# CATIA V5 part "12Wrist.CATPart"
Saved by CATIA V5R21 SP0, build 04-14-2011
Part number: Wrist
Bounding box of the stored display mesh (mm): x -30 to 20.5, y -307.172 to -247.172, z 287.191 to 317.191
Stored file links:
  F:\教程\Robotic_Arm_Arduino_Kinect\机械臂CAD\Arm_Detailed_Design\Wrist.CATPart
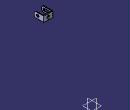
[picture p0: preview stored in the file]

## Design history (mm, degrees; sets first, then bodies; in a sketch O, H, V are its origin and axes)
Body1 (main body)
  DatumSurface1
  DatumCurve1
  DatumCurve2
  Plane1: stored without definition
  Plane2: stored without definition
  DatumCurve3
  Sketch1 on face of DatumSurface1, origin (0, -247.172, 0), H (-1, 0, 0), V (0, 0, 1)
    circle A1 centre (3, 310.6906) radius 1.25
    reference projected circle E1 centre (3, 310.6906) radius 1.25 from edge of DatumCurve2
    circle A2 centre (-5.5, 302.1906) radius 1.25
    circle A3 centre (3, 293.6906) radius 1.25
    circle A4 centre (11.5, 302.1906) radius 1.25
    line L1 (27, 317.1906) -> (-17.5, 317.1906)
    line L2 (-17.5, 317.1906) -> (-17.5, 287.1906)
    line L3 (-17.5, 287.1906) -> (27, 287.1906)
    line L4 (27, 287.1906) -> (27, 317.1906)
    reference intersected line E2 through (0, 302.1906) direction (-1, 0) from Plane1
    reference intersected line E3 through (3, 0) direction (0, -1) from Plane2
    circle A5 centre (3, 302.1906) radius 6
    reference projected circle E4 centre (3, 302.1906) radius 6 from edge of DatumCurve3
    length L2 = 30
    distance L1 E2 = 15
    length L3 = 44.5
    distance L2 E3 = 20.5
    coincidence: A1 E1, A5 E4
    horizontal: L1 H, L3 H
    vertical: L2 V, L4 V
  Pad1: profile Sketch1, direction (0, -1, 0), length 5
  Plane3 to Plane6: stored without definition
  Sketch2 on face of Pad1 from Sketch1.L4, origin (-27, 0, 0), H (0, -1, 0), V (0, 0, 1)
    point P1 (247.172, 317.1906)
    line L1 (247.172, 317.1906) -> (295.172, 317.1906)
    line L2 (307.172, 305.1906) -> (307.172, 299.1906)
    line L3 (295.172, 287.1906) -> (247.172, 287.1906)
    line L4 (247.172, 287.1906) -> (247.172, 317.1906)
    point P2 (307.172, 317.1906)
    reference projected line E1 (247.172, 317.1906) -> (252.172, 317.1906) from edge [face of Pad1 from Sketch1.L4 | face of Pad1 from Sketch1.L1]
    reference projected line E2 (247.172, 287.1906) -> (252.172, 287.1906) from edge [face of Pad1 from Sketch1.L3 | face of Pad1 from Sketch1.L4]
    arc A1 centre (295.172, 305.1906) radius 12 from (295.172, 317.1906) to (307.172, 305.1906) cw
    arc A2 centre (295.172, 299.1906) radius 12 from (295.172, 287.1906) to (307.172, 299.1906) ccw
    line L5 (259.172, 309.6906) -> (294.672, 309.6906)
    line L6 (294.672, 309.6906) -> (294.672, 294.6906)
    line L7 (294.672, 294.6906) -> (259.172, 294.6906)
    line L8 (259.172, 294.6906) -> (259.172, 309.6906)
    reference intersected line E3 through (0, 302.1906) direction (-1, 0) from Plane3
    reference intersected line E4 through (247.172, 0) direction (0, -1) from Plane5
    circle A3 centre (297.422, 306.1906) radius 2.5
    point P14 (297.422, 306.1906)
    reference intersected line E5 through (0, 302.1906) direction (-1, 0) from Plane6
    construction line L9 (276.922, 327.1248) -> (276.922, 250.7347)
    circle A4 centre (256.422, 306.1906) radius 2.5
    axis line L10 (326.5358, 302.1906) -> (252.172, 302.1906)
    circle A5 centre (297.422, 298.1906) radius 2.5
    circle A6 centre (256.422, 298.1906) radius 2.5
    circle A7 centre (249.798, 307.7241) radius 1.25
    point P22 (249.798, 307.7241)
    circle A8 centre (249.672, 297.1906) radius 1.25
    point P23 (249.672, 297.1906)
    reference projected line E6 (247.172, 317.1906) -> (252.172, 317.1906) from edge [face of Pad1 from Sketch1.L4 | face of Pad1 from Sketch1.L1]
    reference projected line E7 (247.172, 287.1906) -> (247.172, 317.1906) from edge [face of Pad2 | face of Pad3]
    distance P1 P2 = 60
    radius A1 = 12
    radius A2 = 12
    distance L5 E3 = 7.5
    length L6 = 15
    length L7 = 35.5
    distance E4 L8 = 12
    radius A3 = 2.5
    distance P14 E5 = 4
    distance L6 L9 = 17.75
    distance P14 L9 = 20.5
    distance L10 L5 = 7.5
    distance P22 E6 = 9.4664
    radius A7 = 1.25
    distance P22 L4 = 2.626
    radius A8 = 1.25
    distance P23 L3 = 10
    distance P23 L4 = 2.5
    horizontal: L1 H, L3 H, L5 H, L7 H, L10 H
    vertical: L2 V, L4 V, L6 V, L8 V, L9 V
    coincidence: L1 E1, L3 E2, L1 P2, L2 P2, L4 E7
    tangency: A1 L1, A1 L2, A2 L3, A2 L2
    symmetry: A3 A4 L9, A3 A5 L10, A4 A6 L10
  Pad2: profile Sketch2, direction (-1, 0, 0), length 3
  DatumSurface2
  Sketch3 on face of Pad1 from Sketch1.L2, origin (17.5, 0, 0), H (0, 1, 0), V (0, 0, 1)
    point P1 (-302.172, 317.1906)
    line L1 (-290.172, 317.1906) -> (-247.172, 317.1906)
    line L2 (-247.172, 317.1906) -> (-247.172, 287.1906)
    line L3 (-247.172, 287.1906) -> (-290.172, 287.1906)
    line L4 (-302.172, 299.1906) -> (-302.172, 305.1906)
    point P2 (-247.172, 317.1906)
    reference projected line E1 (-247.172, 317.1906) -> (-247.172, 287.1906) from edge [face of Pad1 from Sketch1.L2 | start face of Pad1]
    reference projected line E2 (-247.172, 287.1906) -> (-252.172, 287.1906) from edge [face of Pad1 from Sketch1.L2 | face of Pad1 from Sketch1.L3]
    reference projected line E3 (-247.172, 317.1906) -> (-252.172, 317.1906) from edge [face of Pad1 from Sketch1.L1 | face of Pad1 from Sketch1.L2]
    arc A1 centre (-290.172, 299.1906) radius 12 from (-290.172, 287.1906) to (-302.172, 299.1906) cw
    arc A2 centre (-290.172, 305.1906) radius 12 from (-290.172, 317.1906) to (-302.172, 305.1906) ccw
    circle A3 centre (-282.172, 302.1906) radius 7
    point P10 (-282.172, 302.1906)
    circle A4 centre (-249.672, 307.1906) radius 1.25
    point P11 (-249.672, 307.1906)
    circle A5 centre (-249.672, 297.1906) radius 1.25
    point P12 (-249.672, 297.1906)
    radius A1 = 12
    distance P1 P2 = 55
    radius A2 = 12
    distance P10 L2 = 35
    distance P10 L1 = 15
    radius A3 = 7
    radius A4 = 1.25
    distance P11 L2 = 2.5
    distance P11 L1 = 10
    radius A5 = 1.25
    distance P12 L2 = 2.5
    distance P12 L3 = 10
    horizontal: L1 H, L3 H
    vertical: L2 V, L4 V
    coincidence: E1 L2, E2 L3, L1 E3, L1 P1, L4 P1
    tangency: A1 L3, A1 L4, A2 L1, A2 L4
  Pad3: profile Sketch3, direction (1, 0, 0), length 3
  DatumSurface3
  Sketch4 on face of Pad1 from Sketch1.L4, origin (-27, -217.172, 0), H (0, -1, 0), V (0, 0, 1)
    circle A1 centre (3, 310.6906) radius 1.25
    circle A2 centre (-5.5, 302.1906) radius 1.25
    circle A3 centre (3, 293.6906) radius 1.25
    circle A4 centre (11.5, 302.1906) radius 1.25
    line L1 (30, 317.1906) -> (-17.5, 317.1906)
    line L2 (-17.5, 317.1906) -> (-17.5, 287.1906)
    line L3 (-17.5, 287.1906) -> (30, 287.1906)
    line L4 (30, 287.1906) -> (30, 317.1906)
    reference intersected line E1 through (0, 302.1906) direction (-1, 0) from Plane1
    circle A5 centre (3, 302.1906) radius 6
    length L2 = 30
    distance L1 E1 = 15
    length L3 = 47.5
    horizontal: L1 H, L3 H
    vertical: L2 V, L4 V
  Pad4: profile Sketch4, direction (1, 0, 0), length 5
